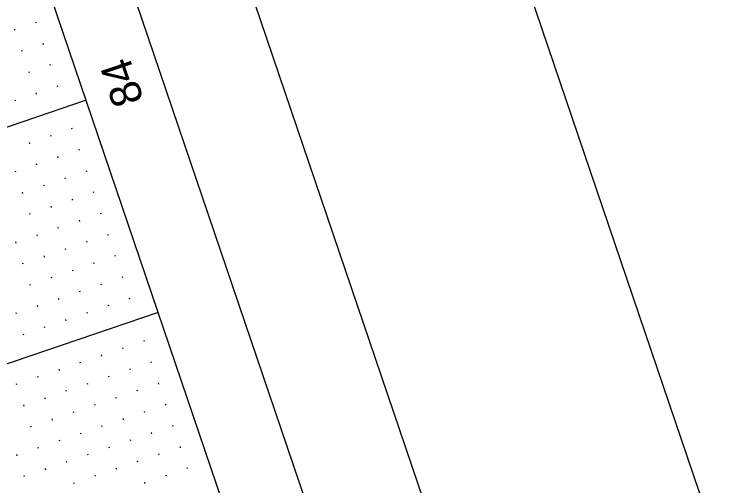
# Model space of a CAD drawing. Extents: x 2150800 to 2152547, y 141860 to 143950.
# Drawn here: x 2151980.1 to 2152140.8, y 143374.3 to 143479.3 of the extents above; entities that cross this region are included whole.
import ezdxf

# ---------------------------------------------------------------- set-up
doc = ezdxf.new("R2010")
doc.units = 0
for name, color, linetype in [('SHT_Plan_Profile_Sheet_Sta_Txt', 7, 'Continuous'), ('SHT_Plot_Shape_Full', 7, 'Continuous'), ('SHT_Plot_Shape_Half', 7, 'Continuous'), ('SHT_Profile_Grid_Major', 7, 'Continuous'), ('SHT_Profile_Grid_Minor', 7, 'Continuous'), ('SHT_Sheet_Border', 7, 'Continuous')]:
    doc.layers.add(name, color=color, linetype=linetype)

msp = doc.modelspace()

# ---------------------------------------------------------------- linework, layer by layer
at = {"layer": 'SHT_Plot_Shape_Full'}
msp.add_lwpolyline([(2151378.63, 141860.13), (2150800.36, 143564.71), (2151936.74, 143950.23), (2152515.02, 142245.65)], close=True, dxfattribs=at)
at = {"layer": 'SHT_Plot_Shape_Half'}
msp.add_lwpolyline([(2151391.39, 141950.92), (2150845.24, 143560.8), (2151886.93, 143914.19), (2152433.08, 142304.31)], close=True, dxfattribs=at)
at = {"layer": 'SHT_Profile_Grid_Major'}
for p, q in [((2151996.07, 143460.19), (2151565.19, 143314.01)), ((2152012.13, 143412.84), (2151538.64, 143252.21))]:
    msp.add_line(p, q, dxfattribs=at)
at = {"layer": 'SHT_Profile_Grid_Minor'}
for p, q in [((2151984.95, 143477.4), (2151984.87, 143477.64)), ((2151980.22, 143475.8), (2151980.14, 143476.03)), ((2151986.56, 143472.67), (2151986.48, 143472.9)), ((2151981.82, 143471.06), (2151981.74, 143471.3)), ((2151988.16, 143467.93), (2151988.08, 143468.17)), ((2151983.43, 143466.33), (2151983.35, 143466.56)), ((2151989.77, 143463.2), (2151989.69, 143463.43)), ((2151985.04, 143461.59), (2151984.96, 143461.83)), ((2151980.3, 143459.98), (2151980.22, 143460.22)), ((2151992.98, 143453.73), (2151992.9, 143453.96)), ((2151988.25, 143452.12), (2151988.17, 143452.36)), ((2151983.51, 143450.51), (2151983.43, 143450.75)), ((2151994.59, 143448.99), (2151994.51, 143449.23)), ((2151989.85, 143447.39), (2151989.77, 143447.62)), ((2151985.12, 143445.78), (2151985.04, 143446.02)), ((2151980.38, 143444.17), (2151980.3, 143444.41)), ((2151996.2, 143444.26), (2151996.12, 143444.49)), ((2151991.46, 143442.65), (2151991.38, 143442.89)), ((2151986.73, 143441.04), (2151986.65, 143441.28)), ((2151981.99, 143439.44), (2151981.91, 143439.67)), ((2151997.8, 143439.52), (2151997.72, 143439.76)), ((2151993.07, 143437.92), (2151992.99, 143438.15)), ((2151988.33, 143436.31), (2151988.25, 143436.55)), ((2151983.6, 143434.7), (2151983.52, 143434.94)), ((2151999.41, 143434.79), (2151999.33, 143435.02)), ((2151994.67, 143433.18), (2151994.59, 143433.42)), ((2151989.94, 143431.57), (2151989.86, 143431.81)), ((2151985.2, 143429.97), (2151985.12, 143430.2)), ((2152001.01, 143430.05), (2152000.93, 143430.29)), ((2151980.47, 143428.36), (2151980.39, 143428.6)), ((2151996.28, 143428.45), (2151996.2, 143428.68)), ((2151991.54, 143426.84), (2151991.46, 143427.08)), ((2151986.81, 143425.23), (2151986.73, 143425.47)), ((2152002.62, 143425.32), (2152002.54, 143425.55)), ((2151982.07, 143423.63), (2151981.99, 143423.86)), ((2151997.89, 143423.71), (2151997.81, 143423.95)), ((2151993.15, 143422.1), (2151993.07, 143422.34)), ((2151988.42, 143420.5), (2151988.34, 143420.74)), ((2152004.23, 143420.58), (2152004.15, 143420.82)), ((2151983.68, 143418.89), (2151983.6, 143419.13)), ((2151999.49, 143418.98), (2151999.41, 143419.21)), ((2151994.76, 143417.37), (2151994.68, 143417.61)), ((2151990.02, 143415.76), (2151989.94, 143416)), ((2152005.83, 143415.85), (2152005.75, 143416.08)), ((2151985.29, 143414.16), (2151985.21, 143414.39)), ((2152001.1, 143414.24), (2152001.02, 143414.48)), ((2151980.55, 143412.55), (2151980.47, 143412.79)), ((2151996.36, 143412.63), (2151996.28, 143412.87)), ((2151991.63, 143411.03), (2151991.55, 143411.27)), ((2151986.89, 143409.42), (2151986.81, 143409.66)), ((2151982.16, 143407.82), (2151982.08, 143408.05)), ((2152009.05, 143406.38), (2152008.97, 143406.61)), ((2152004.31, 143404.77), (2152004.23, 143405.01)), ((2151999.58, 143403.16), (2151999.5, 143403.4)), ((2151994.84, 143401.56), (2151994.76, 143401.8)), ((2152010.65, 143401.64), (2152010.57, 143401.88)), ((2151990.11, 143399.95), (2151990.03, 143400.19)), ((2152005.92, 143400.04), (2152005.84, 143400.27)), ((2151985.37, 143398.35), (2151985.29, 143398.58)), ((2152001.18, 143398.43), (2152001.1, 143398.67)), ((2151980.64, 143396.74), (2151980.56, 143396.98)), ((2151996.45, 143396.82), (2151996.37, 143397.06)), ((2152012.26, 143396.91), (2152012.18, 143397.14)), ((2151991.71, 143395.22), (2151991.63, 143395.45)), ((2152007.52, 143395.3), (2152007.44, 143395.54)), ((2151986.98, 143393.61), (2151986.9, 143393.85)), ((2152002.79, 143393.69), (2152002.71, 143393.93)), ((2151982.24, 143392), (2151982.16, 143392.24)), ((2151998.05, 143392.09), (2151997.97, 143392.33)), ((2152013.87, 143392.17), (2152013.78, 143392.41)), ((2151993.32, 143390.48), (2151993.24, 143390.72)), ((2152009.13, 143390.57), (2152009.05, 143390.8)), ((2151988.58, 143388.88), (2151988.5, 143389.11)), ((2152004.4, 143388.96), (2152004.31, 143389.2)), ((2151983.85, 143387.27), (2151983.77, 143387.51)), ((2151999.66, 143387.35), (2151999.58, 143387.59)), ((2152015.47, 143387.44), (2152015.39, 143387.67)), ((2151994.93, 143385.75), (2151994.85, 143385.98)), ((2152010.74, 143385.83), (2152010.66, 143386.07)), ((2151990.19, 143384.14), (2151990.11, 143384.38)), ((2152006, 143384.22), (2152005.92, 143384.46)), ((2151985.46, 143382.53), (2151985.38, 143382.77)), ((2152001.27, 143382.62), (2152001.19, 143382.86)), ((2152017.08, 143382.7), (2152017, 143382.94)), ((2151980.72, 143380.93), (2151980.64, 143381.17)), ((2151996.53, 143381.01), (2151996.45, 143381.25)), ((2152012.34, 143381.1), (2152012.26, 143381.33)), ((2151991.8, 143379.41), (2151991.72, 143379.64)), ((2152007.61, 143379.49), (2152007.53, 143379.73)), ((2151987.06, 143377.8), (2151986.98, 143378.04)), ((2152002.87, 143377.88), (2152002.79, 143378.12)), ((2152018.68, 143377.97), (2152018.6, 143378.2)), ((2151982.33, 143376.19), (2151982.25, 143376.43)), ((2151998.14, 143376.28), (2151998.06, 143376.51)), ((2152013.95, 143376.36), (2152013.87, 143376.6)), ((2151993.4, 143374.67), (2151993.32, 143374.91)), ((2152009.21, 143374.76), (2152009.13, 143374.99))]:
    msp.add_line(p, q, dxfattribs=at)
at = {"layer": 'SHT_Sheet_Border'}
msp.add_line((2152361.51, 142382.99), (2151939.85, 143625.91), dxfattribs=at)
msp.add_lwpolyline([(2151383.74, 142051.28), (2150877.75, 143542.79), (2151872.09, 143880.12), (2152378.08, 142388.61)], close=True, dxfattribs=at)

# ---------------------------------------------------------------- texts
at = {"layer": 'SHT_Plan_Profile_Sheet_Sta_Txt'}
msp.add_text('84', height=7, rotation=108.7393, dxfattribs=at).set_placement((2152008.99, 143460.24))

doc.saveas('drawing.dxf')
